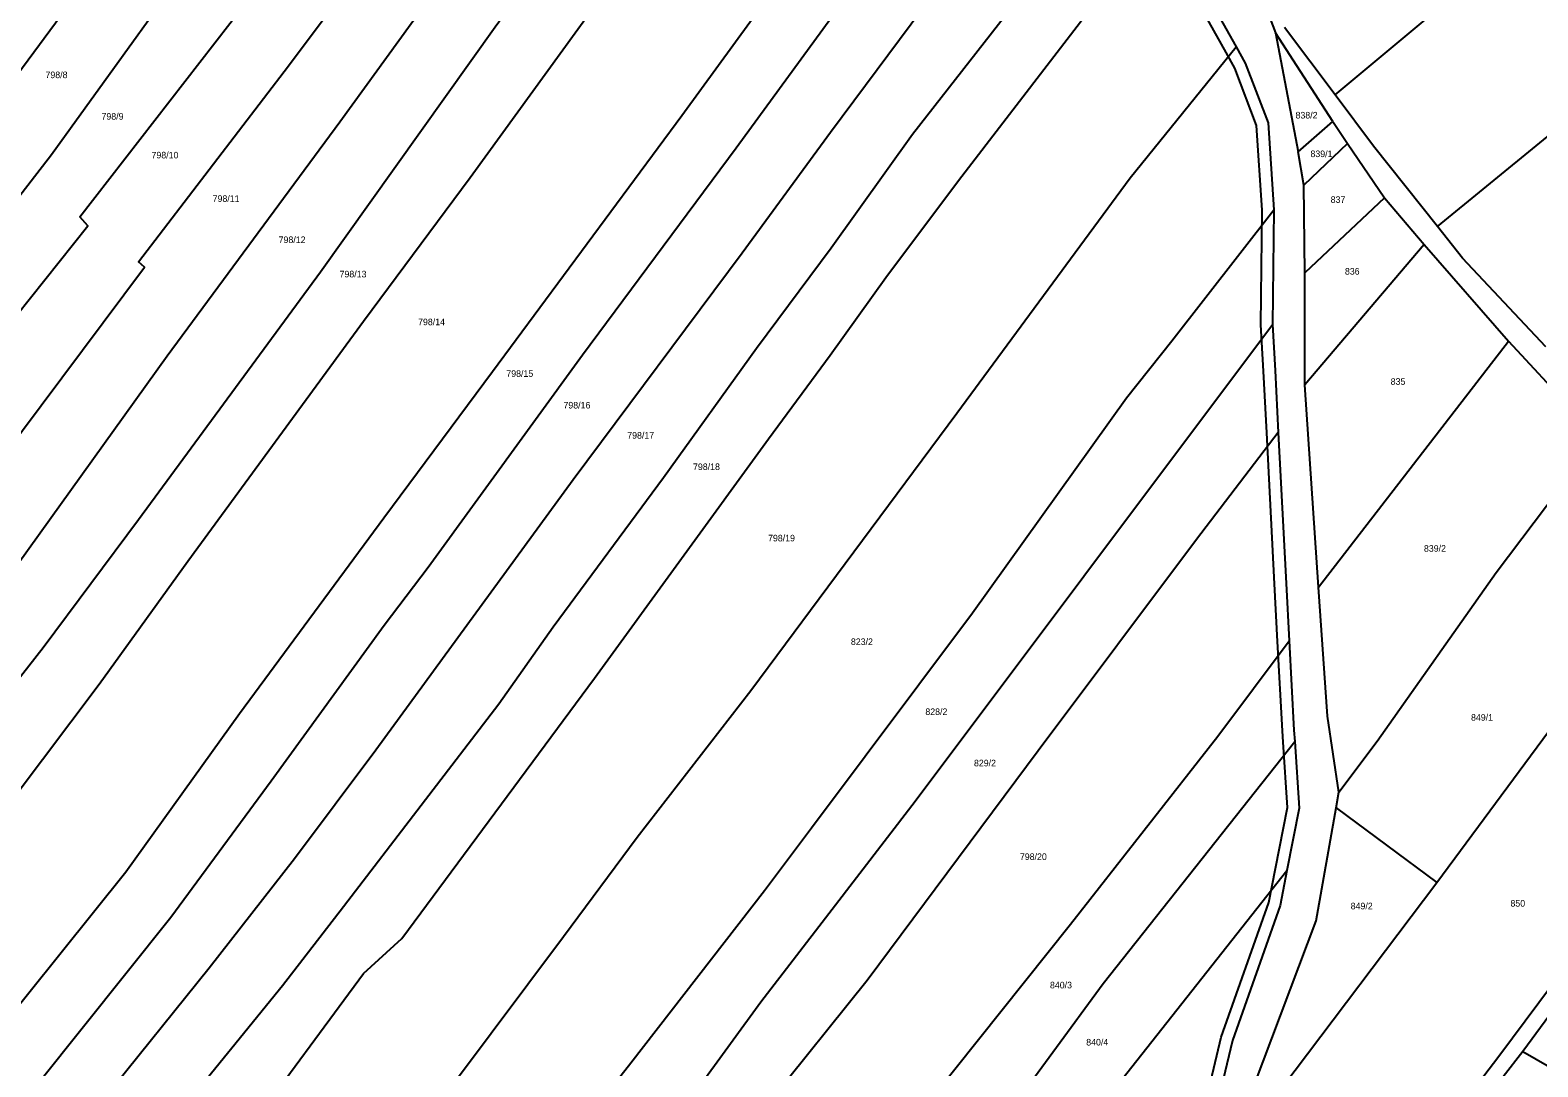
# Model space of a CAD drawing. Extents: x -7483133 to -743169, y -11317770 to -1127091.
# Drawn here: x -747897.9 to -747508.3, y -1131617.3 to -1131349.4 of the extents above; entities that cross this region are included whole.
import ezdxf

# ---------------------------------------------------------------- set-up
doc = ezdxf.new("R2010")
doc.units = 0
for name, color, linetype in [('_TRASA_vedení kabelu_CEZ', 7, 'Continuous'), ('Hranice parcel', 7, 'Continuous'), ('Parcelní čísla', 7, 'Continuous')]:
    doc.layers.add(name, color=color, linetype=linetype)

msp = doc.modelspace()

# ---------------------------------------------------------------- linework, layer by layer
at = {"layer": '_TRASA_vedení kabelu_CEZ'}
msp.add_lwpolyline([(-747599.82, -1131650.35), (-747590.15, -1131609.62), (-747577.85, -1131574.83), (-747576.11, -1131566), (-747573.02, -1131550.26), (-747574.14, -1131533.4), (-747574.33, -1131530.46), (-747575.58, -1131507.34), (-747576.38, -1131492.52), (-747578.4, -1131453.5), (-747579.22, -1131437.56), (-747579.88, -1131425.59), (-747579.54, -1131395.96), (-747581.01, -1131374.06), (-747586.67, -1131359.23), (-747588.9, -1131355.23), (-747596.45, -1131341.71), (-747599.17, -1131336.75), (-747586.05, -1131328.3), (-747611.25, -1131294.46), (-747635.1, -1131256.91), (-747661.52, -1131218.38), (-747680.96, -1131197.51)], dxfattribs=at)
at = {"layer": 'Hranice parcel'}
for p, q in [((-747579.59, -1131341), (-747576.14, -1131350.08)), ((-747576.14, -1131350.08), (-747570.26, -1131380.88)), ((-747561.31, -1131373.03), (-747576.14, -1131350.08)), ((-747560.74, -1131366.12), (-747573.75, -1131348.78)), ((-747570.26, -1131380.88), (-747561.31, -1131373.03)), ((-747561.31, -1131373.03), (-747557.5, -1131378.68)), ((-747557.5, -1131378.68), (-747568.77, -1131389.44)), ((-747557.5, -1131378.68), (-747547.95, -1131392.74)), ((-747568.77, -1131389.44), (-747570.26, -1131380.88)), ((-747568.57, -1131412.15), (-747568.77, -1131389.44)), ((-747547.95, -1131392.74), (-747568.57, -1131412.15)), ((-747547.95, -1131392.74), (-747537.66, -1131404.8)), ((-747576.54, -1131395.88), (-747576.88, -1131425.52)), ((-747537.66, -1131404.8), (-747568.52, -1131441.05)), ((-747537.66, -1131404.8), (-747515.93, -1131429.75)), ((-747568.52, -1131441.05), (-747568.57, -1131412.15)), ((-747564.97, -1131493.37), (-747515.93, -1131429.75)), ((-747515.93, -1131429.75), (-747492.83, -1131454.72)), ((-747564.97, -1131493.37), (-747568.52, -1131441.05)), ((-747534.47, -1131569.66), (-747469.89, -1131482.38)), ((-747560.43, -1131550.33), (-747559.72, -1131546.32)), ((-747560.43, -1131550.33), (-747534.47, -1131569.66)), ((-747495.81, -1131591.02), (-747512.18, -1131613.29))]:
    msp.add_line(p, q, dxfattribs=at)
for points in [[(-748039.41, -1131527.57), (-748021.11, -1131510.35), (-748001.42, -1131490.57), (-747960.37, -1131438.84), (-747946.8, -1131421.49), (-747906.82, -1131368.28), (-747888.73, -1131343.94), (-747857, -1131301.23), (-747832.91, -1131270.59), (-747818.02, -1131250.97), (-747795.27, -1131221.64), (-747787.74, -1131212.45)], [(-748030.59, -1131550.68), (-748006.8, -1131528.34), (-747986.12, -1131504.66), (-747956.18, -1131464.19), (-747938.32, -1131440.9), (-747892.39, -1131381.59), (-747846.71, -1131318.11), (-747774.62, -1131223.12)], [(-748020.54, -1131577.02), (-748001.95, -1131555.56), (-747973.86, -1131518.8), (-747960.03, -1131500.15), (-747932.73, -1131464.51), (-747901.57, -1131423.28), (-747883.06, -1131399.99), (-747885.07, -1131397.67), (-747846.34, -1131347.72), (-747814.92, -1131307.18), (-747804.7, -1131292.12), (-747768.78, -1131245.74)], [(-748006.35, -1131589.51), (-747976.31, -1131553.75), (-747942.87, -1131510.32), (-747895.09, -1131446.4), (-747868.39, -1131410.63), (-747869.95, -1131409.28), (-747831.18, -1131358.67), (-747781.73, -1131292.56), (-747753.62, -1131256.62)], [(-747560.74, -1131366.12), (-747532.83, -1131342.86), (-747438.82, -1131264.87), (-747425.11, -1131256.95)], [(-747991.94, -1131600.7), (-747981.03, -1131587.21), (-747950.23, -1131550.08), (-747903.91, -1131491.23), (-747862.5, -1131433.61), (-747817.95, -1131373.1), (-747784.2, -1131326.61), (-747760.62, -1131294.4), (-747739.39, -1131266.83)], [(-747972.95, -1131605.36), (-747952.16, -1131580.99), (-747925.8, -1131548.77), (-747894.55, -1131508.92), (-747869.95, -1131475.83), (-747822.94, -1131411.83), (-747777.73, -1131348.55), (-747747.86, -1131307.75), (-747735.67, -1131291.6), (-747724.81, -1131277.29)], [(-747953.56, -1131610.11), (-747936.63, -1131589.74), (-747927.22, -1131580.6), (-747917.02, -1131567.38), (-747880.11, -1131518.39), (-747857.18, -1131486.6), (-747811.82, -1131424.61), (-747784.23, -1131387.47), (-747748.68, -1131338.4), (-747710.63, -1131287.46)], [(-747915.42, -1131619.45), (-747873.23, -1131566.86), (-747843.82, -1131525.97), (-747806.53, -1131475.44), (-747778.43, -1131437.61), (-747729.49, -1131371.5), (-747693.71, -1131322.2), (-747669.82, -1131292.66)], [(-747534.26, -1131400.17), (-747480.38, -1131356.14), (-747430.3, -1131312.29), (-747401.97, -1131292.55)], [(-747895.76, -1131621.42), (-747861.58, -1131578.6), (-747835.67, -1131543.4), (-747806.42, -1131503.18), (-747795.07, -1131488.14), (-747755.24, -1131433.32), (-747715.49, -1131379.82), (-747681.87, -1131333.76), (-747656, -1131302.39)], [(-747879, -1131625.66), (-747851.66, -1131591.69), (-747829.65, -1131563.42), (-747808.64, -1131535.34), (-747757.65, -1131465.52), (-747713.97, -1131406.96), (-747691.09, -1131375.78), (-747664.28, -1131339.63), (-747646.2, -1131316.75), (-747642.09, -1131312.59)], [(-747860.06, -1131629.88), (-747832.75, -1131596.26), (-747816.97, -1131575.83), (-747776.82, -1131523.47), (-747762.78, -1131503.59), (-747734.31, -1131465.05), (-747710.2, -1131431.58), (-747690.98, -1131405.7), (-747669.96, -1131376.28), (-747627.04, -1131321.32)], [(-747842.01, -1131634.16), (-747811.79, -1131593.14), (-747801.87, -1131584.09), (-747752.07, -1131516.87), (-747707.12, -1131455.02), (-747691.23, -1131433.37), (-747676.82, -1131413.33), (-747658, -1131388.25), (-747620.26, -1131339), (-747608.88, -1131328.87)], [(-747597.93, -1131333.8), (-747595.82, -1131336.69), (-747586.28, -1131353.77)], [(-747806.67, -1131645.86), (-747760.08, -1131583.56), (-747741.05, -1131557.9), (-747711.67, -1131520.04), (-747658.45, -1131448.35), (-747613.7, -1131387.55), (-747586.28, -1131353.77)], [(-747586.28, -1131353.77), (-747583.94, -1131357.96), (-747578.05, -1131373.41), (-747576.54, -1131395.88)], [(-747534.26, -1131400.17), (-747550.8, -1131379.36), (-747560.74, -1131366.12)], [(-747772.35, -1131654.05), (-747742.69, -1131616.2), (-747708.15, -1131571.7), (-747696.05, -1131555.49), (-747654.43, -1131499.96), (-747614.66, -1131444.39), (-747602.9, -1131429.72), (-747576.54, -1131395.88)], [(-747506.23, -1131431.25), (-747527.79, -1131408.31), (-747534.26, -1131400.17)], [(-747751.97, -1131658.69), (-747725.51, -1131622.95), (-747709.1, -1131600.51), (-747691.54, -1131577.63), (-747669.23, -1131548.64), (-747625.65, -1131490.48), (-747576.88, -1131425.52)], [(-747576.88, -1131425.52), (-747576.22, -1131437.4), (-747575.4, -1131453.35)], [(-747575.4, -1131453.35), (-747596.53, -1131480.99), (-747637.49, -1131535.62), (-747681.61, -1131594.97), (-747707.2, -1131626.86), (-747733.77, -1131662.83)], [(-747575.4, -1131453.35), (-747573.38, -1131492.36), (-747572.58, -1131507.18)], [(-747559.72, -1131546.32), (-747549.84, -1131533.09), (-747519.12, -1131489.53), (-747492.83, -1131454.72)], [(-747559.72, -1131546.32), (-747562.72, -1131526.64), (-747564.97, -1131493.37)], [(-747698.69, -1131671.28), (-747664.74, -1131625.11), (-747629.09, -1131580.38), (-747591, -1131531.84), (-747572.58, -1131507.18)], [(-747572.58, -1131507.18), (-747571.34, -1131530.28), (-747571.15, -1131533.2)], [(-747443.45, -1131514.26), (-747480.55, -1131563.87), (-747518.42, -1131614.59), (-747550, -1131656.02), (-747584.22, -1131698.64)], [(-747680.04, -1131675.66), (-747646.64, -1131631.19), (-747620.64, -1131595.74), (-747571.15, -1131533.2)], [(-747571.15, -1131533.2), (-747570, -1131550.45), (-747573.17, -1131566.58)], [(-747582.84, -1131630.56), (-747581.53, -1131621.85), (-747565.63, -1131579.59), (-747560.43, -1131550.33)], [(-747660.92, -1131680.14), (-747626.14, -1131633.64), (-747573.17, -1131566.58)], [(-747573.17, -1131566.58), (-747574.95, -1131575.62), (-747587.27, -1131610.47), (-747596.84, -1131650.77)], [(-747582.84, -1131630.56), (-747574.44, -1131622.7), (-747534.47, -1131569.66)], [(-747512.18, -1131613.29), (-747532.53, -1131639.52), (-747561.47, -1131683.37), (-747579.28, -1131700.12)], [(-747512.18, -1131613.29), (-747502.43, -1131618.94), (-747504.69, -1131623.44), (-747559.41, -1131702.48)]]:
    msp.add_lwpolyline(points, dxfattribs=at)

# ---------------------------------------------------------------- texts
at = {"layer": 'Parcelní čísla'}
for s, p in [('798/8', (-747893.97, -1131361.83)), ('798/9', (-747879.5, -1131372.56)), ('838/2', (-747570.94, -1131372.25)), ('798/10', (-747866.57, -1131382.57)), ('839/1', (-747567.08, -1131382.23)), ('798/11', (-747850.78, -1131393.81)), ('837', (-747561.86, -1131394.06)), ('798/12', (-747833.72, -1131404.44)), ('836', (-747558.18, -1131412.59)), ('798/13', (-747817.98, -1131413.31)), ('798/14', (-747797.69, -1131425.66)), ('798/15', (-747774.88, -1131439.01)), ('835', (-747546.35, -1131441.06)), ('798/16', (-747760.12, -1131447.18)), ('798/17', (-747743.64, -1131454.98)), ('798/18', (-747726.64, -1131463.09)), ('798/19', (-747707.25, -1131481.52)), ('839/2', (-747537.76, -1131484.19)), ('823/2', (-747685.84, -1131508.29)), ('828/2', (-747666.6, -1131526.38)), ('849/1', (-747525.59, -1131527.85)), ('829/2', (-747654.04, -1131539.64)), ('798/20', (-747642.17, -1131563.83)), ('850', (-747515.4, -1131575.88)), ('849/2', (-747556.69, -1131576.58)), ('840/3', (-747634.4, -1131597.01)), ('840/4', (-747625.03, -1131611.76))]:
    msp.add_text(s, height=1.7, dxfattribs=at).set_placement(p)

doc.saveas('drawing.dxf')
